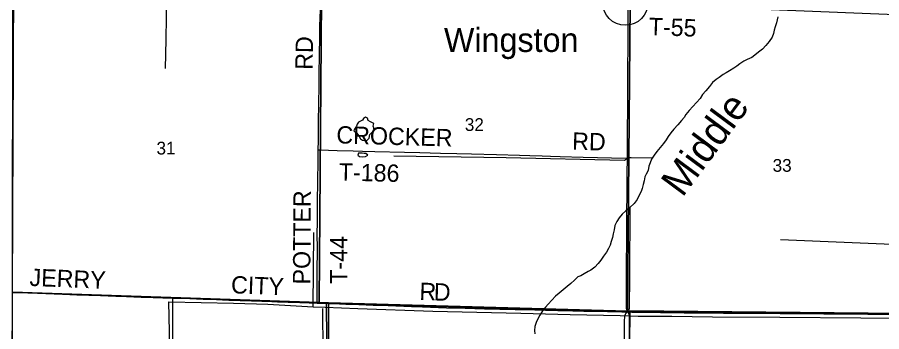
# Model space of a CAD drawing. Extents: x 1443599 to 1910620, y 1028088 to 1361369.
# Drawn here: x 1620320 to 1635252, y 1187739 to 1193177 of the extents above; entities that cross this region are included whole.
import ezdxf

# ---------------------------------------------------------------- set-up
doc = ezdxf.new("R2010")
doc.units = 0
for name, color, linetype in [('GM_X_Major_River', 7, 'Continuous'), ('GM_X_Major_River_Text', 7, 'Continuous'), ('GM_X_Minor_Lake', 7, 'Continuous'), ('GM_X_Minor_River', 7, 'Continuous'), ('GM_X_Section', 7, 'Continuous'), ('GM_X_Section_Text', 7, 'Continuous'), ('GM_X_Township', 7, 'Continuous'), ('GM_X_Township_Road', 7, 'Continuous'), ('GM_X_Township_Road_Text', 7, 'Continuous'), ('GM_X_Unincorporated', 7, 'Continuous'), ('GM_X_Unincorporated_Text', 7, 'Continuous')]:
    doc.layers.add(name, color=color, linetype=linetype)

msp = doc.modelspace()

# ---------------------------------------------------------------- linework, layer by layer
at = {"layer": 'GM_X_Major_River'}
for points in [[(1633459, 1193183), (1633449, 1193133), (1633433, 1193083), (1633409, 1193009), (1633394, 1192955), (1633382, 1192899), (1633358, 1192833), (1633308, 1192759), (1633251, 1192690), (1633193, 1192626), (1633125, 1192575), (1633061, 1192521), (1633008, 1192483), (1632928, 1192447), (1632872, 1192417), (1632804, 1192369), (1632748, 1192331), (1632695, 1192297), (1632625, 1192249), (1632565, 1192217), (1632511, 1192185), (1632442, 1192135), (1632392, 1192103), (1632328, 1192049), (1632278, 1191981), (1632217, 1191903), (1632155, 1191843), (1632115, 1191775), (1632051, 1191703), (1631988, 1191635), (1631924, 1191563), (1631870, 1191495), (1631839, 1191445), (1631793, 1191391), (1631729, 1191315), (1631663, 1191241), (1631610, 1191179), (1631564, 1191117), (1631530, 1191059), (1631482, 1190995), (1631369, 1190858), (1631319, 1190792), (1631276, 1190726), (1631250, 1190662), (1631232, 1190602), (1631216, 1190528), (1631182, 1190466), (1631161, 1190416), (1631147, 1190346), (1631131, 1190283), (1631113, 1190217), (1631096, 1190163), (1631064, 1190101), (1631026, 1190025), (1630976, 1189957), (1630901, 1189889), (1630833, 1189829), (1630771, 1189771), (1630715, 1189709), (1630676, 1189645), (1630642, 1189575), (1630630, 1189503), (1630612, 1189434), (1630601, 1189368), (1630579, 1189302), (1630559, 1189234), (1630535, 1189180)], [(1630535, 1189180), (1630498, 1189116), (1630448, 1189044), (1630398, 1188978), (1630352, 1188918), (1630297, 1188854), (1630229, 1188802), (1630179, 1188780), (1630113, 1188740), (1630054, 1188706), (1630004, 1188688), (1629944, 1188632), (1629882, 1188574), (1629816, 1188524), (1629749, 1188464), (1629681, 1188408), (1629619, 1188354), (1629552, 1188286), (1629490, 1188216), (1629446, 1188164), (1629394, 1188098), (1629347, 1188028), (1629311, 1187960), (1629283, 1187898), (1629263, 1187830), (1629254, 1187763), (1629260, 1187701)]]:
    msp.add_lwpolyline(points, dxfattribs=at)
at = {"layer": 'GM_X_Minor_Lake'}
for p, q in [((1626190, 1191331), (1626180, 1191295)), ((1626311, 1190819), (1626279, 1190825))]:
    msp.add_line(p, q, dxfattribs=at)
for points in [[(1626180, 1191295), (1626144, 1191243), (1626135, 1191212), (1626155, 1191190), (1626181, 1191176), (1626221, 1191126), (1626251, 1191076), (1626285, 1191054), (1626355, 1191043), (1626400, 1191089), (1626410, 1191151), (1626456, 1191193), (1626486, 1191223), (1626480, 1191266), (1626470, 1191292), (1626480, 1191342), (1626424, 1191366), (1626380, 1191394), (1626371, 1191434), (1626334, 1191447), (1626298, 1191429), (1626286, 1191399), (1626248, 1191381), (1626212, 1191363), (1626190, 1191331)], [(1626279, 1190825), (1626247, 1190825), (1626212, 1190827), (1626200, 1190795), (1626234, 1190769), (1626290, 1190763), (1626335, 1190771), (1626377, 1190793), (1626341, 1190823), (1626311, 1190819)]]:
    msp.add_lwpolyline(points, dxfattribs=at)
at = {"layer": 'GM_X_Minor_River'}
for points in [[(1622643, 1196306), (1622924, 1196093), (1622916, 1195603), (1622915, 1195056), (1622902, 1194168), (1622898, 1193559), (1622887, 1192792), (1622873, 1192291)], [(1631285, 1190740), (1630926, 1190749), (1630874, 1190746), (1630844, 1190722), (1630810, 1190700), (1628764, 1190748), (1626825, 1190775)], [(1630901, 1189889), (1630894, 1188722), (1630890, 1188132), (1630862, 1188106), (1630830, 1188060), (1630818, 1188038), (1630808, 1188002), (1630801, 1187922), (1630802, 1187568), (1630804, 1186828), (1630823, 1186237)], [(1625429, 1188170), (1625445, 1189455)], [(1636118, 1189218), (1633504, 1189326)], [(1622968, 1186357), (1622959, 1187020), (1622949, 1187736), (1622938, 1188255), (1624057, 1188232), (1624649, 1188213)], [(1624649, 1188213), (1625429, 1188170), (1625636, 1188165), (1626201, 1188139), (1627499, 1188093), (1629017, 1188061), (1629868, 1188039), (1630734, 1188018), (1631044, 1188007), (1631625, 1188007), (1632332, 1187997), (1633492, 1187992), (1634892, 1187980), (1636114, 1187974)], [(1625612, 1186311), (1625605, 1187393), (1625600, 1188143)]]:
    msp.add_lwpolyline(points, dxfattribs=at)
at = {"layer": 'GM_X_Section'}
for points in [[(1620261, 1193747), (1625576, 1193507), (1625533, 1188242), (1620239, 1188421)], [(1625576, 1193507), (1630908, 1193407), (1630860, 1188096), (1625697, 1188238), (1625533, 1188242)], [(1630908, 1193407), (1636205, 1193194), (1636192, 1188050), (1630900, 1188098), (1630860, 1188096)], [(1620239, 1188421), (1625533, 1188242), (1625697, 1188238), (1625680, 1182986), (1620214, 1183081)], [(1630860, 1188096), (1630900, 1188098), (1630847, 1182935), (1630833, 1182933), (1625680, 1182986), (1625697, 1188238)], [(1630900, 1188098), (1636192, 1188050), (1636193, 1187880), (1636172, 1182849), (1630847, 1182935)]]:
    msp.add_lwpolyline(points, close=True, dxfattribs=at)
at = {"layer": 'GM_X_Township'}
for points in [[(1636189, 1188034), (1630892, 1188083), (1625691, 1188229), (1625518, 1188234), (1622993, 1188324), (1620237, 1188424), (1620246, 1193716), (1620295, 1199077), (1620327, 1204365), (1620392, 1209603), (1620391, 1209712), (1620428, 1214993), (1620439, 1220361), (1625693, 1220296), (1625907, 1220301), (1631102, 1220200), (1636477, 1220086)], [(1635965, 1156490), (1631322, 1156526), (1630660, 1156530), (1630464, 1156532), (1625342, 1156563), (1625188, 1156564), (1622574, 1156580), (1620027, 1156604), (1620071, 1159262), (1620081, 1161924), (1620105, 1164447), (1620106, 1164621), (1620109, 1167154), (1620123, 1172454), (1620177, 1177790), (1620194, 1180346), (1620213, 1183050), (1620230, 1185626), (1620237, 1188424), (1622993, 1188324), (1625518, 1188234), (1625691, 1188229), (1630892, 1188083), (1636189, 1188034)]]:
    msp.add_lwpolyline(points, dxfattribs=at)
at = {"layer": 'GM_X_Township_Road'}
for points in [[(1625520, 1190885), (1625521, 1191041), (1625525, 1191369), (1625535, 1191992), (1625536, 1192222), (1625540, 1192501), (1625545, 1192862), (1625549, 1193026), (1625557, 1193305), (1625560, 1193502), (1625560, 1193528)], [(1630860, 1190738), (1630860, 1190747), (1630861, 1190944), (1630865, 1191880), (1630868, 1192307), (1630870, 1192668), (1630873, 1193012), (1630874, 1193259), (1630876, 1193357), (1630880, 1193389), (1630882, 1193399)], [(1625501, 1188235), (1625500, 1188268), (1625499, 1188301), (1625500, 1188563), (1625501, 1188826), (1625504, 1189121), (1625503, 1189482), (1625504, 1189581), (1625504, 1189728), (1625508, 1190007), (1625514, 1190319), (1625519, 1190713), (1625520, 1190860), (1625520, 1190885)], [(1625520, 1190885), (1625547, 1190884), (1625843, 1190875), (1626122, 1190867), (1626286, 1190863), (1626499, 1190856), (1627008, 1190845), (1627271, 1190837), (1627632, 1190828), (1627911, 1190820), (1628166, 1190814)], [(1628166, 1190814), (1628600, 1190804), (1628994, 1190793), (1629175, 1190785), (1629388, 1190781), (1629529, 1190777)], [(1629529, 1190777), (1629700, 1190772), (1630094, 1190758), (1630833, 1190739), (1630860, 1190738)], [(1630868, 1188081), (1630860, 1188092), (1630853, 1188107), (1630847, 1188122), (1630844, 1188138), (1630843, 1188154), (1630842, 1188220), (1630844, 1188548), (1630846, 1188942), (1630849, 1189270), (1630852, 1189796), (1630856, 1190124), (1630858, 1190468), (1630860, 1190738)], [(1620239, 1188419), (1620281, 1188418), (1620503, 1188411), (1620667, 1188406), (1621101, 1188386), (1621348, 1188379), (1621758, 1188364), (1622020, 1188353), (1622209, 1188348), (1622463, 1188338), (1622668, 1188333), (1623004, 1188322)], [(1623004, 1188322), (1623152, 1188317), (1623300, 1188313), (1623529, 1188304), (1623652, 1188301), (1623972, 1188287), (1624366, 1188272), (1624719, 1188260), (1624817, 1188256), (1624998, 1188249), (1625219, 1188243), (1625365, 1188240), (1625431, 1188236), (1625501, 1188235)], [(1623028, 1183053), (1623027, 1183088), (1623025, 1183186), (1623023, 1183778), (1623021, 1184173), (1623020, 1184764), (1623018, 1185077), (1623018, 1185241), (1623019, 1185422), (1623017, 1186162), (1623016, 1186474), (1623015, 1186605), (1623012, 1187214), (1623009, 1187740), (1623006, 1188101), (1623005, 1188249), (1623005, 1188298), (1623004, 1188322)], [(1625501, 1188235), (1625547, 1188233), (1625662, 1188231)], [(1625676, 1183002), (1625676, 1183039), (1625674, 1183483), (1625672, 1184139), (1625667, 1184550), (1625663, 1184763), (1625660, 1184944), (1625662, 1185173), (1625663, 1185321), (1625667, 1185584), (1625666, 1185879), (1625667, 1186355), (1625666, 1186733), (1625666, 1187291), (1625665, 1187439), (1625665, 1187603), (1625665, 1187734), (1625663, 1188095), (1625662, 1188194), (1625662, 1188231)], [(1625662, 1188231), (1625777, 1188228), (1625998, 1188218), (1626113, 1188214), (1626220, 1188210), (1626466, 1188201), (1626728, 1188191), (1626859, 1188186), (1627130, 1188176), (1627319, 1188169), (1627737, 1188155), (1628057, 1188145), (1628393, 1188136), (1628918, 1188124), (1629115, 1188121), (1629263, 1188118), (1629444, 1188112), (1629509, 1188110), (1629657, 1188106), (1629919, 1188101), (1630108, 1188097), (1630280, 1188093), (1630518, 1188090), (1630707, 1188088), (1630765, 1188085), (1630838, 1188082), (1630868, 1188081)], [(1630852, 1182954), (1630854, 1182964), (1630857, 1183046), (1630859, 1183374), (1630862, 1183539), (1630865, 1183719), (1630868, 1184047), (1630870, 1184343), (1630874, 1184638), (1630877, 1185262), (1630878, 1185606), (1630882, 1186197), (1630886, 1186673), (1630891, 1187248), (1630894, 1187477), (1630896, 1187953), (1630894, 1188019), (1630892, 1188035), (1630887, 1188051), (1630880, 1188065), (1630868, 1188081)], [(1630868, 1188081), (1630937, 1188079), (1631068, 1188077), (1631166, 1188076), (1631281, 1188075), (1631429, 1188071), (1631667, 1188070), (1631839, 1188067), (1631979, 1188067), (1632291, 1188064), (1632521, 1188061), (1632947, 1188060), (1633497, 1188054), (1633670, 1188053), (1633908, 1188053), (1634252, 1188050), (1634687, 1188050), (1635024, 1188049), (1635401, 1188050), (1635803, 1188049), (1636124, 1188047), (1636186, 1188049), (1636208, 1188049)]]:
    msp.add_lwpolyline(points, dxfattribs=at)
at = {"layer": 'GM_X_Unincorporated'}
msp.add_circle((1630824, 1193432), 393, dxfattribs=at)

# ---------------------------------------------------------------- texts
at = {"layer": 'GM_X_Major_River_Text'}
msp.add_text('Middle', height=500.3, rotation=53.3792, dxfattribs=at).set_placement((1631809, 1190049))
at = {"layer": 'GM_X_Section_Text'}
for s, p in [('32', (1628051, 1191211)), ('31', (1622725, 1190804)), ('33', (1633368, 1190505))]:
    msp.add_text(s, height=221, rotation=0, dxfattribs=at).set_placement(p)
at = {"layer": 'GM_X_Township_Road_Text'}
for s, rotation, p in [('T-55', 357.9038, (1631224, 1192871)), ('RD', 89.0109, (1625421, 1192267)), ('CROCKER', 358.4082, (1625829, 1190997)), ('RD', 358.5194, (1629902, 1190887)), ('T-186', 358.5964, (1625871, 1190354)), ('POTTER', 89.637, (1625381, 1188556)), ('T-44', 90, (1626024, 1188569)), ('JERRY', 357.7625, (1620528, 1188532)), ('CITY', 357.7544, (1624008, 1188405)), ('R', 357.9036, (1627263, 1188290)), ('D', 358.1911, (1627511, 1188281))]:
    msp.add_text(s, height=300, rotation=rotation, dxfattribs=at).set_placement(p)
at = {"layer": 'GM_X_Unincorporated_Text'}
msp.add_text('Wingston', height=417, rotation=0, dxfattribs=at).set_placement((1627690, 1192577))

doc.saveas('drawing.dxf')
